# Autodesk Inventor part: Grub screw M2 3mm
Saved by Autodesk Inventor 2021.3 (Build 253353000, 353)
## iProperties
Created: 2022-07
Part Number: Grub screw M2 3mm
Material: Generic
Document SubType Name: Modeling
Designer: Administrator
Density: 1 g/cm^3
Appearance: Default
Title: Grub screw M2 3mm
Author: Administrator
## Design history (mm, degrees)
feature "Body1"
body "Solid1"
